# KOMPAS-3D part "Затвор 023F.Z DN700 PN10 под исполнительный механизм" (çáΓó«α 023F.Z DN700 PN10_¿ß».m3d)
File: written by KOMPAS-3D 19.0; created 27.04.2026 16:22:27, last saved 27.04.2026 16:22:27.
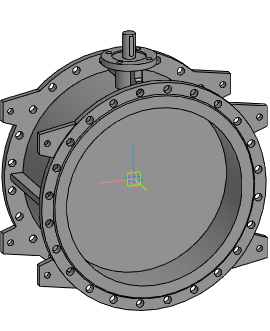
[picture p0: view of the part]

Document properties: Автор: Евгений; Полное имя файла: Z:\3.Личные\kachalov\3d для проектировщиков\1.7 Тип 023F.Z Затвор дисковый поворотный фланцевый с двумя эксцентриками\Затвор 023F.Z DN200-DN1600_исп\_stp_Затвор 023F.Z DN200-DN1600_исп\Затвор 023F.Z DN700 PN10_исп.m3d

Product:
- Part/product: Затвор 023F.Z DN700 PN10 под исполнительный механизм

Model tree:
1. Операция без истории:1  (labels: Затвор 023F.Z DN700 PN10 под исполнительный механизм)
